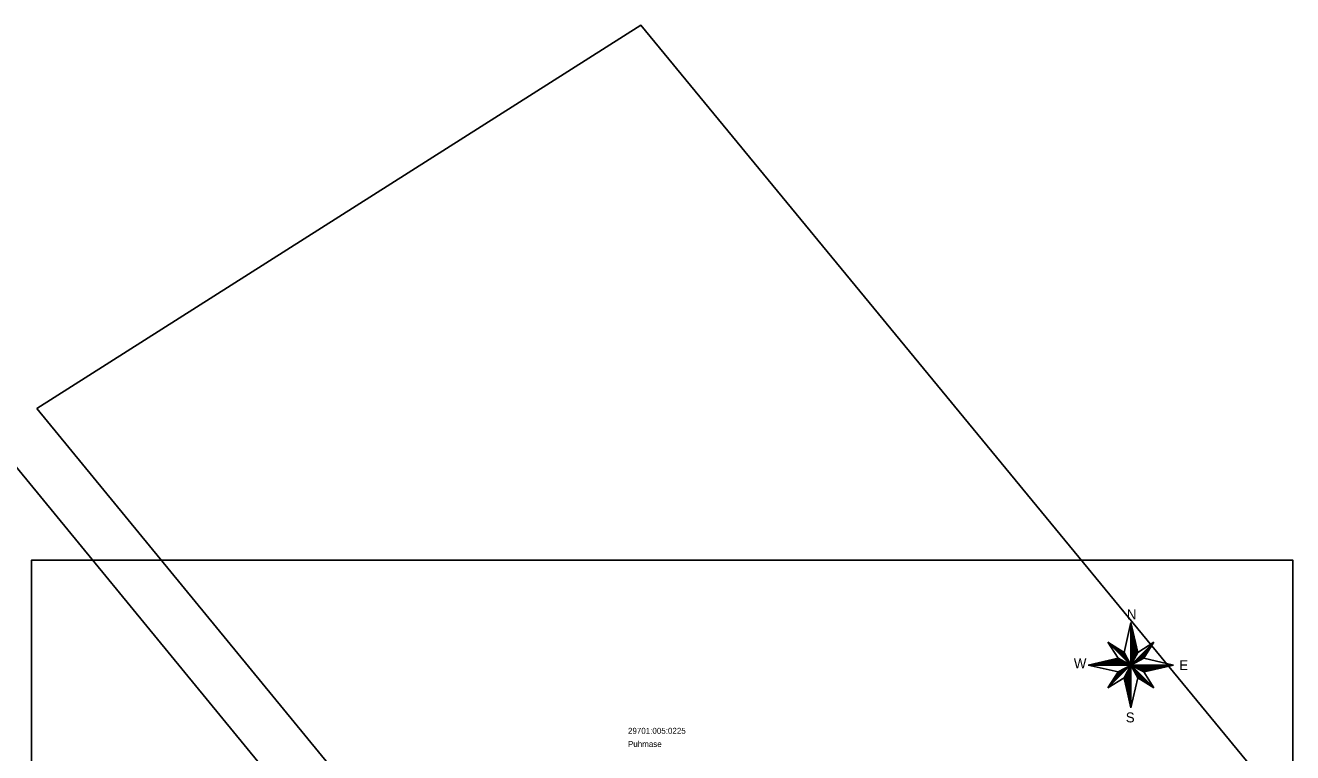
# Model space of a CAD drawing. Extents: x 529142 to 529430, y 6557605 to 6557874.
# Drawn here: x 529238.7 to 529429.6, y 6557764.3 to 6557874 of the extents above; entities that cross this region are included whole.
import ezdxf

# ---------------------------------------------------------------- set-up
doc = ezdxf.new("R2010")
doc.units = 0
doc.layers.add('PIIR', color=7, linetype='Continuous')
doc.layers.add('VORMISTUS', color=7, linetype='Continuous')

msp = doc.modelspace()

# ---------------------------------------------------------------- linework, layer by layer
at = {"layer": 'PIIR'}
for points in [[(529240.36, 6557816.2), (529348.66, 6557684.15), (529355.79, 6557690.82), (529382.39, 6557716.11), (529429.5, 6557754.74), (529425.44, 6557759.68), (529331.39, 6557873.99)], [(529141.76, 6557753.61), (529263.81, 6557604.78), (529342.84, 6557678.62), (529233.56, 6557811.89)]]:
    msp.add_lwpolyline(points, close=True, dxfattribs=at)
at = {"layer": 'VORMISTUS'}
msp.add_lwpolyline([(529239.6, 6557654.86), (529239.6, 6557793.36), (529429.6, 6557793.36), (529429.6, 6557654.86)], close=True, dxfattribs=at)
for points in [[(529405.23, 6557783.98), (529404.19, 6557779.46)], [(529405.23, 6557783.98), (529406.25, 6557779.46)], [(529405.23, 6557783.98), (529405.23, 6557771.1)], [(529405.23, 6557783.94), (529405.23, 6557783.94)], [(529405.27, 6557783.75), (529405.27, 6557777.63)], [(529405.32, 6557783.53), (529405.32, 6557777.72)], [(529405.37, 6557783.31), (529405.37, 6557777.82)], [(529405.42, 6557783.09), (529405.42, 6557777.91)], [(529405.47, 6557782.87), (529405.47, 6557778.01)], [(529401.77, 6557780.98), (529408.67, 6557774.1)], [(529401.77, 6557780.98), (529404.19, 6557779.46)], [(529401.77, 6557780.98), (529403.29, 6557778.56)], [(529408.67, 6557780.98), (529401.77, 6557774.1)], [(529405.52, 6557782.65), (529405.52, 6557778.1)], [(529405.57, 6557782.42), (529405.57, 6557778.19)], [(529405.62, 6557782.2), (529405.62, 6557778.29)], [(529405.67, 6557781.98), (529405.67, 6557778.38)], [(529405.72, 6557781.76), (529405.72, 6557778.48)], [(529405.77, 6557781.54), (529405.77, 6557778.57)], [(529405.82, 6557781.32), (529405.82, 6557778.66)], [(529405.87, 6557781.1), (529405.87, 6557778.76)], [(529408.67, 6557780.98), (529406.25, 6557779.46)], [(529408.67, 6557780.98), (529407.15, 6557778.56)], [(529401.95, 6557780.86), (529405.15, 6557777.67)], [(529402.14, 6557780.74), (529405.07, 6557777.82)], [(529402.33, 6557780.62), (529404.99, 6557777.97)], [(529402.52, 6557780.5), (529404.91, 6557778.12)], [(529402.71, 6557780.38), (529404.82, 6557778.27)], [(529402.9, 6557780.26), (529404.74, 6557778.43)], [(529403.1, 6557780.13), (529404.65, 6557778.59)], [(529403.29, 6557780.02), (529404.57, 6557778.74)], [(529403.5, 6557779.89), (529404.48, 6557778.9)], [(529403.68, 6557779.77), (529404.4, 6557779.06)], [(529403.87, 6557779.65), (529404.32, 6557779.21)], [(529404.06, 6557779.53), (529404.24, 6557779.36)], [(529404.19, 6557779.46), (529405.23, 6557777.54)], [(529405.23, 6557777.54), (529406.25, 6557779.46)], [(529408.55, 6557780.79), (529405.35, 6557777.6)], [(529408.43, 6557780.6), (529405.5, 6557777.68)], [(529408.31, 6557780.41), (529405.65, 6557777.76)], [(529408.19, 6557780.23), (529405.8, 6557777.84)], [(529405.92, 6557780.87), (529405.92, 6557778.85)], [(529408.08, 6557780.04), (529405.95, 6557777.92)], [(529405.97, 6557780.65), (529405.97, 6557778.95)], [(529406.02, 6557780.43), (529406.02, 6557779.04)], [(529406.07, 6557780.21), (529406.07, 6557779.14)], [(529407.96, 6557779.85), (529406.1, 6557778)], [(529406.12, 6557779.99), (529406.12, 6557779.23)], [(529406.17, 6557779.77), (529406.17, 6557779.32)], [(529407.83, 6557779.65), (529406.26, 6557778.09)], [(529407.72, 6557779.47), (529406.41, 6557778.17)], [(529407.59, 6557779.27), (529406.57, 6557778.25)], [(529407.47, 6557779.08), (529406.72, 6557778.33)], [(529398.79, 6557777.54), (529403.29, 6557778.56)], [(529398.79, 6557777.54), (529403.29, 6557776.52)], [(529398.79, 6557777.54), (529411.65, 6557777.54)], [(529399, 6557777.59), (529405.13, 6557777.59)], [(529399.22, 6557777.64), (529405.03, 6557777.64)], [(529399.45, 6557777.69), (529404.94, 6557777.69)], [(529399.67, 6557777.74), (529404.84, 6557777.74)], [(529399.89, 6557777.79), (529404.75, 6557777.79)], [(529400.11, 6557777.84), (529404.65, 6557777.84)], [(529400.33, 6557777.89), (529404.56, 6557777.89)], [(529400.55, 6557777.94), (529404.46, 6557777.94)], [(529400.77, 6557777.99), (529404.37, 6557777.99)], [(529400.99, 6557778.04), (529404.27, 6557778.04)], [(529401.21, 6557778.09), (529404.18, 6557778.09)], [(529401.43, 6557778.14), (529404.08, 6557778.14)], [(529401.65, 6557778.19), (529403.99, 6557778.19)], [(529401.87, 6557778.24), (529403.89, 6557778.24)], [(529405.05, 6557777.45), (529401.88, 6557774.28)], [(529404.91, 6557777.37), (529402, 6557774.47)], [(529402.09, 6557778.29), (529403.8, 6557778.29)], [(529404.76, 6557777.29), (529402.12, 6557774.66)], [(529404.61, 6557777.21), (529402.23, 6557774.84)], [(529402.31, 6557778.34), (529403.7, 6557778.34)], [(529404.46, 6557777.13), (529402.35, 6557775.03)], [(529402.53, 6557778.39), (529403.61, 6557778.39)], [(529402.75, 6557778.44), (529403.51, 6557778.44)], [(529402.97, 6557778.49), (529403.42, 6557778.49)], [(529403.2, 6557778.54), (529403.32, 6557778.54)], [(529405.23, 6557777.54), (529403.29, 6557778.56)], [(529403.29, 6557776.52), (529405.23, 6557777.54)], [(529405.23, 6557777.54), (529404.19, 6557775.62)], [(529405.02, 6557777.17), (529405.02, 6557771.96)], [(529405.07, 6557777.26), (529405.07, 6557771.75)], [(529405.12, 6557777.35), (529405.12, 6557771.53)], [(529405.17, 6557777.44), (529405.17, 6557771.31)], [(529407.15, 6557778.56), (529405.23, 6557777.54)], [(529405.23, 6557777.54), (529407.15, 6557776.52)], [(529406.25, 6557775.62), (529405.23, 6557777.54)], [(529405.31, 6557777.37), (529408.47, 6557774.21)], [(529405.32, 6557777.49), (529411.42, 6557777.49)], [(529405.39, 6557777.22), (529408.28, 6557774.33)], [(529405.41, 6557777.44), (529411.2, 6557777.44)], [(529405.51, 6557777.39), (529410.98, 6557777.39)], [(529405.6, 6557777.34), (529410.76, 6557777.34)], [(529405.69, 6557777.29), (529410.54, 6557777.29)], [(529405.79, 6557777.24), (529410.32, 6557777.24)], [(529405.88, 6557777.19), (529410.1, 6557777.19)], [(529405.98, 6557777.14), (529409.88, 6557777.14)], [(529407.35, 6557778.89), (529406.87, 6557778.41)], [(529407.24, 6557778.7), (529407.02, 6557778.49)], [(529411.65, 6557777.54), (529407.15, 6557778.56)], [(529411.65, 6557777.54), (529407.15, 6557776.52)], [(529401.77, 6557774.1), (529403.29, 6557776.52)], [(529401.77, 6557774.1), (529404.19, 6557775.62)], [(529404.31, 6557777.06), (529402.47, 6557775.22)], [(529404.15, 6557776.97), (529402.59, 6557775.42)], [(529404.01, 6557776.9), (529402.71, 6557775.61)], [(529403.85, 6557776.81), (529402.84, 6557775.81)], [(529403.7, 6557776.73), (529402.96, 6557775.99)], [(529403.55, 6557776.66), (529403.07, 6557776.18)], [(529403.4, 6557776.58), (529403.19, 6557776.37)], [(529405.23, 6557771.1), (529404.19, 6557775.62)], [(529404.22, 6557775.69), (529404.22, 6557775.44)], [(529404.27, 6557775.78), (529404.27, 6557775.22)], [(529404.32, 6557775.87), (529404.32, 6557775.01)], [(529404.37, 6557775.97), (529404.37, 6557774.79)], [(529404.42, 6557776.06), (529404.42, 6557774.57)], [(529404.47, 6557776.15), (529404.47, 6557774.36)], [(529404.52, 6557776.24), (529404.52, 6557774.14)], [(529404.57, 6557776.34), (529404.57, 6557773.92)], [(529404.62, 6557776.43), (529404.62, 6557773.7)], [(529404.67, 6557776.52), (529404.67, 6557773.49)], [(529404.72, 6557776.61), (529404.72, 6557773.27)], [(529404.77, 6557776.7), (529404.77, 6557773.05)], [(529404.82, 6557776.8), (529404.82, 6557772.83)], [(529404.87, 6557776.89), (529404.87, 6557772.62)], [(529404.92, 6557776.98), (529404.92, 6557772.4)], [(529404.97, 6557777.07), (529404.97, 6557772.18)], [(529405.23, 6557771.1), (529406.25, 6557775.62)], [(529405.47, 6557777.07), (529408.1, 6557774.45)], [(529405.55, 6557776.92), (529407.91, 6557774.57)], [(529405.63, 6557776.77), (529407.72, 6557774.69)], [(529405.71, 6557776.62), (529407.53, 6557774.81)], [(529405.79, 6557776.46), (529407.32, 6557774.94)], [(529405.87, 6557776.31), (529407.13, 6557775.06)], [(529405.96, 6557776.16), (529406.93, 6557775.18)], [(529406.04, 6557776.01), (529406.74, 6557775.3)], [(529406.07, 6557777.09), (529409.66, 6557777.09)], [(529406.11, 6557775.86), (529406.55, 6557775.42)], [(529406.16, 6557777.04), (529409.44, 6557777.04)], [(529406.19, 6557775.71), (529406.36, 6557775.54)], [(529408.67, 6557774.1), (529406.25, 6557775.62)], [(529406.26, 6557776.99), (529409.22, 6557776.99)], [(529406.35, 6557776.94), (529409, 6557776.94)], [(529406.45, 6557776.89), (529408.78, 6557776.89)], [(529406.54, 6557776.84), (529408.56, 6557776.84)], [(529406.64, 6557776.79), (529408.33, 6557776.79)], [(529406.73, 6557776.74), (529408.11, 6557776.74)], [(529406.82, 6557776.69), (529407.89, 6557776.69)], [(529406.92, 6557776.64), (529407.67, 6557776.64)], [(529407.01, 6557776.59), (529407.45, 6557776.59)], [(529407.11, 6557776.54), (529407.23, 6557776.54)], [(529408.67, 6557774.1), (529407.15, 6557776.52)]]:
    msp.add_lwpolyline(points, dxfattribs=at)

# ---------------------------------------------------------------- texts
at = {"layer": 'PIIR'}
for s, p in [('29701:005:0225', (529329.45, 6557767.18)), ('Puhmase ', (529329.45, 6557765.19))]:
    msp.add_text(s, height=0.9, dxfattribs=at).set_placement(p)
at = {"layer": 'VORMISTUS'}
for s, p in [('N', (529404.62, 6557784.43)), ('W', (529396.63, 6557777.04)), ('E', (529412.5, 6557776.78)), ('S', (529404.45, 6557768.9))]:
    msp.add_text(s, height=1.5, dxfattribs=at).set_placement(p)

doc.saveas('drawing.dxf')
